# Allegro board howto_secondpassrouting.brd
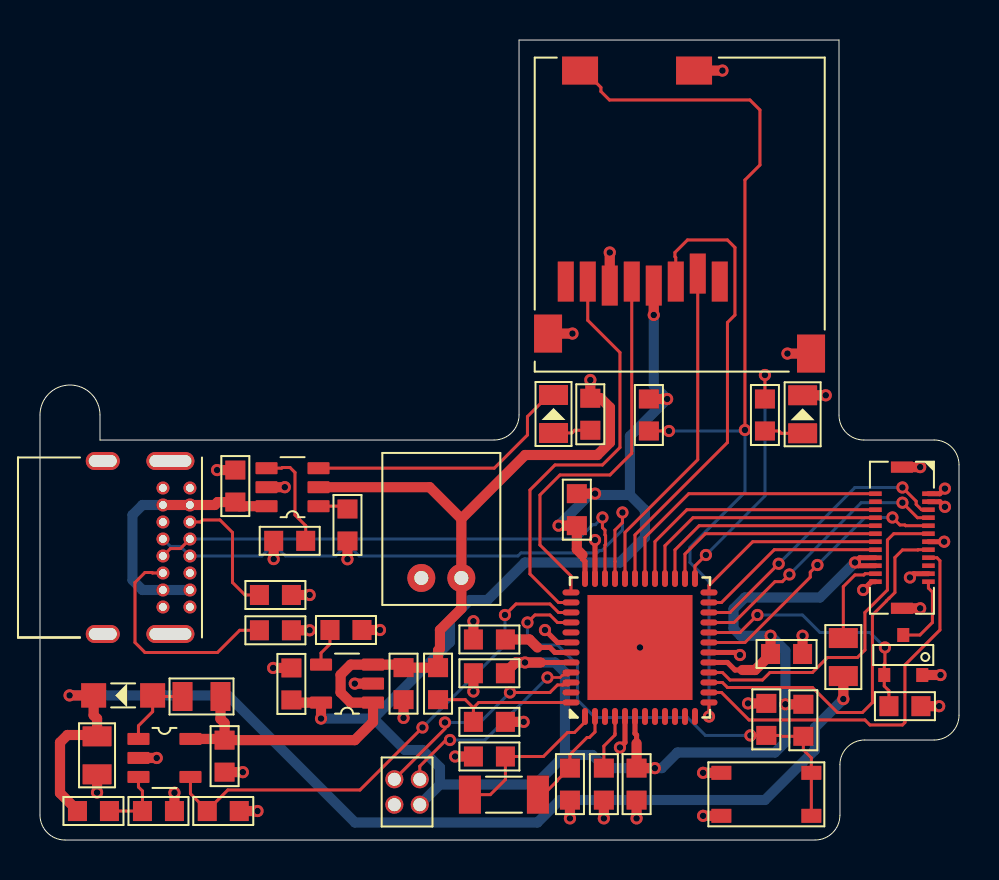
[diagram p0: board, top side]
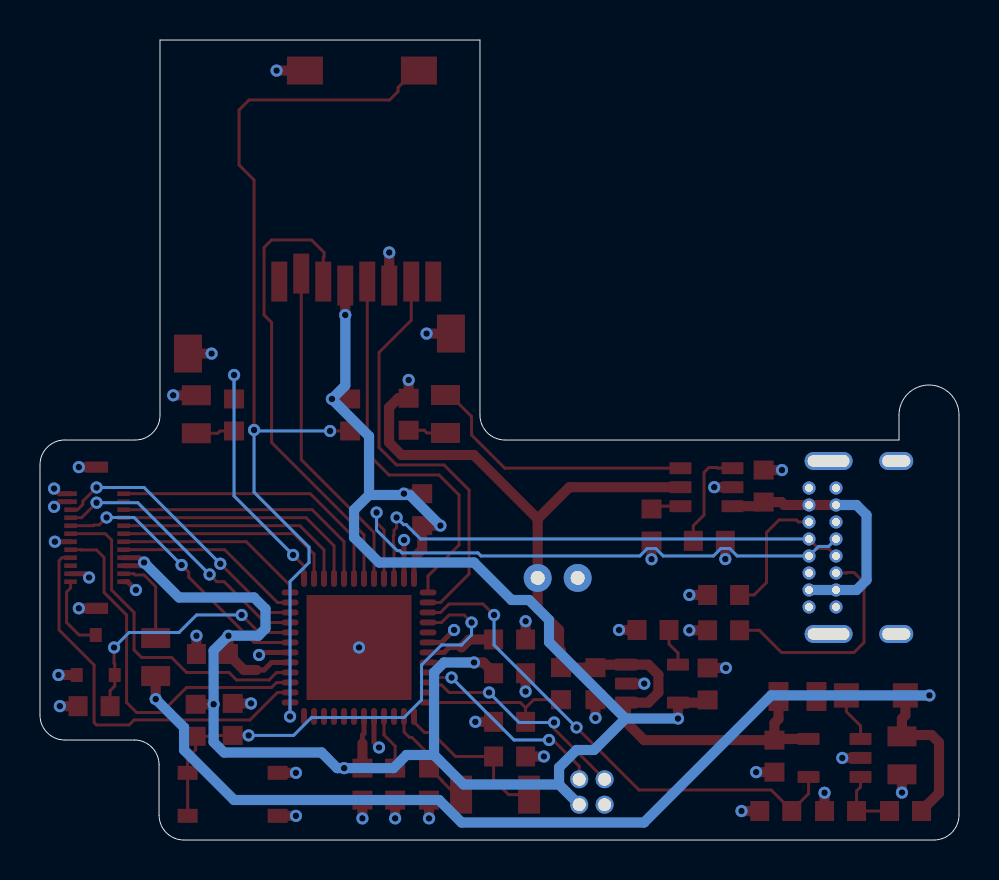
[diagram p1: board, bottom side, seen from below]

Outline 45.95 x 40 mm; copper layers: TOP, L2, L3, BOTTOM. Coordinates in mm from the lower left corner of the outline.
Outline path: 0,21.25 0,1.25 arc(0.37,0.37) 1.25,0 38.76,0 arc(39.64,0.36) 40,1.24 40,3.76 arc(40.36,4.64) 41.24,5 44.71,5 arc(45.59,5.36) 45.95,6.24 45.95,18.76 arc(45.59,19.64) 44.71,20 41.19,20 arc(40.32,20.36) 39.95,21.24 39.95,40 23.95,40 23.95,21.25 arc(23.59,20.37) 22.7,20 3,20 3,21.25 arc(1.5,22.75) 0,21.25

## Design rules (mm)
constraint set DEFAULT: min track width 0.127

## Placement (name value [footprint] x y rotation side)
C15  1uF  [CAP0603]  9.77 17.7 90 top
C16  1uF  [CAP0603]  18.18 7.82 270 top
C19  10uF  [CAP0805]  2.85 4.23 270 top
C20  2.2uF  [CAP0603]  12.57 7.8 90 top
C21  470pF  [CAP0603]  15.3 10.5 0 top
C23  100nF  [CAP0603]  22.47 8.34 180 top
C24  100nF  [CAP0603]  26.84 16.52 90 top
C25  100nF  [CAP0603]  37.33 9.3 0 top
C26  100nF  [CAP0603]  29.83 2.79 270 top
C27  1uF  [CAP0603]  22.47 10.03 180 top
C28  1uF  [CAP0603]  28.2 2.79 270 top
C29  100nF  [CAP0603]  36.32 6.03 90 top
C32  1uF  [CAP0603]  9.23 4.19 270 top
C33  9pF  [CAP0603]  22.47 4.18 180 top
C34  9pF  [CAP0603]  26.5 2.79 270 top
D1  GREEN  [DIO0805]  38.14 21.29 90 top
D2  GREEN  [DIO0805]  25.68 21.3 90 top
D3  SCHOTTKY_DIODE  [SOD-123FL]  4.16 7.23 180 top
J1  -  [USB4085-GF-A]  1.4 14.63 270 top
J2  HEADER VERT 2X2  [2X2-HEADER-50MIL-VERT]  18.36 2.4 270 top
J3  DF37NB-24DS-0.4V  [DF37NB-24DS-0]  43.1 15.11 270 top
J4  2-PIN-CON  [S2B-PH-K]  19.07 13.1 0 top
L1  10uH  [IND0805]  8.08 7.18 180 top
M2  NMOS  [SOT-23-3]  43.17 9.25 0 top
R7  86.6k  [RES0603]  2.67 1.45 0 top
R8  10k  [RES0603]  5.92 1.45 0 top
R9  5.1k  [RES0603]  11.77 12.25 0 top
R10  5.1k  [RES0603]  11.77 10.49 0 top
R11  5.1k  [RES0603]  12.49 14.96 180 top
R12  10k  [RES0603]  38.17 5.99 270 top
R13  10k  [RES0603]  9.16 1.45 0 top
R14  10k  [RES0603]  36.25 21.25 270 top
R15  1.5k  [RES0603]  27.52 21.29 270 top
R16  100k  [RES0603]  19.9 7.82 270 top
R17  100k  [RES0603]  22.47 5.91 0 top
R18  10k  [RES0603]  30.45 21.25 270 top
R19  150R  [RES0805]  40.17 9.15 90 top
R20  10k  [RES0603]  43.25 6.69 0 top
R21  10k  [RES0603]  15.38 15.75 270 top
S1  SPST-NO  [PTS815-SJM-250-SMTR-LFS]  36.32 2.28 0 top
SD2  -  [MEM2061]  30.14 27.92 0 top
U2  BQ21040  [SOT-23-6]  12.63 17.64 180 top
U4  MIC5205-3.3YM5-TR  [SOT-23-5]  15.35 7.82 180 top
U5  AP3012_IC  [SOT-23-5]  6.22 4.1 0 top
U7  ATSAMD21G18A-MF  [48QFN_7X7]  30 9.63 90 top
Y2  32.768 kHz  [2-SMD]  23.2 2.27 0 top

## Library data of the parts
C15 C16 C19-C21 C23-C29 C32-C34 = CAP1: tolerance: 10%
D1 D2 = SML-210MTT86
D3 = SCHOTTKY_DIODE
J1 = USB4085-GF-A
J2 = HEADER VERT 2X2
J3 = DF37NB-24DS-0.4V
J4 = 2-PIN-CON
L1 = IND: tolerance: 20%
M2 = NMOS
R7-R21 = RES1: tolerance: 1%
S1 = PTS815 SJM 250 SMTR LFS
SD2 = MEM2061
U2 = BQ21040
U4 = MIC5205-3.3YM5-TR
U5 = AP3012_IC
U7 = ATSAMD21G18A-MF
Y2 = CC5V-T1A-32.768KHZ-9PF: tolerance: 20%

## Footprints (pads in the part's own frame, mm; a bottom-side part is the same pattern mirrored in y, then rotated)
2-SMD
  rect 1.1x1.9 smd: 1(-1.7,0) 2(1.7,0)
2X2-HEADER-50MIL-VERT
  round 0.9 hole 0.65: 1(-0.635,0.635) 2(-0.635,-0.635) 3(0.635,0.635) 4(0.635,-0.635)
48QFN_7X7
  oval 0.851x0.3 smd: 1(-3.45,2.75) 2(-3.45,2.25) 3(-3.45,1.75) 4(-3.45,1.25) 5(-3.45,0.75) 6(-3.45,0.25) 7(-3.45,-0.25) 8(-3.45,-0.75) 9(-3.45,-1.25) 10(-3.45,-1.75) 11(-3.45,-2.25) 12(-3.45,-2.75) 25(3.45,-2.75) 26(3.45,-2.25) 27(3.45,-1.75) 28(3.45,-1.25) 29(3.45,-0.75) 30(3.45,-0.25) 31(3.45,0.25) 32(3.45,0.75) 33(3.45,1.25) 34(3.45,1.75) 35(3.45,2.25) 36(3.45,2.75)
  oval 0.3x0.851 smd: 13(-2.75,-3.45) 14(-2.25,-3.45) 15(-1.75,-3.45) 16(-1.25,-3.45) 17(-0.75,-3.45) 18(-0.25,-3.45) 19(0.25,-3.45) 20(0.75,-3.45) 21(1.25,-3.45) 22(1.75,-3.45) 23(2.25,-3.45) 24(2.75,-3.45) 37(2.75,3.45) 38(2.25,3.45) 39(1.75,3.45) 40(1.25,3.45) 41(0.75,3.45) 42(0.25,3.45) 43(-0.25,3.45) 44(-0.75,3.45) 45(-1.25,3.45) 46(-1.75,3.45) 47(-2.25,3.45) 48(-2.75,3.45)
  rect 5.25x5.25 smd: 49(0,0)
CAP0603
  rect 0.95x1.001 smd: 1(-0.8,0) 2(0.8,0)
CAP0805
  rrect 1x1.45 smd: 1(-0.95,0) 2(0.95,0)
DF37NB-24DS-0
  rect 0.23x0.63 smd: 1(-2.2,1.325) 2(-2.2,-1.325) 3(-1.8,1.325) 4(-1.8,-1.325) 5(-1.4,1.325) 6(-1.4,-1.325) 7(-1,1.325) 8(-1,-1.325) 9(-0.6,1.325) 10(-0.6,-1.325) 11(-0.2,1.325) 12(-0.2,-1.325) 13(0.2,1.325) 14(0.2,-1.325) 15(0.6,1.325) 16(0.6,-1.325) 17(1,1.325) 18(1,-1.325) 19(1.4,1.325) 20(1.4,-1.325) 21(1.8,1.325) 22(1.8,-1.325) 23(2.2,1.325) 24(2.2,-1.325)
  rect 0.56x1.1 smd: 25(-3.53,0) 26(3.53,0)
DIO0805
  rrect 1x1.45 smd: 1(-0.95,0) 2(0.95,0)
IND0805
  rrect 1x1.45 smd: 1(-0.95,0) 2(0.95,0)
MEM2061
  rect 0.8x2 smd: 1(3.85,0) 2(2.75,0.4) 3(1.65,0) 4(0.55,-0.2) 5(-0.55,0) 6(-1.65,-0.2) 7(-2.75,0) 8(-3.85,0)
  rect 1.4x1.9 smd: P1(-4.735,-2.6) P2(8.415,-3.6)
  rect 1.8x1.4 smd: SW1(-3.135,10.55) SW2(2.565,10.55)
PTS815-SJM-250-SMTR-LFS
  rect 1x0.7 smd: 1(-2.25,1.075) 2(2.25,1.075) 3(-2.25,-1.075) 4(2.25,-1.075)
RES0603
  rect 0.95x1.001 smd: 1(-0.8,0) 2(0.8,0)
RES0805
  rrect 1x1.45 smd: 1(-0.95,0) 2(0.95,0)
S2B-PH-K
  round 1.4 hole 0.7: 1(2,0) 2(0,0)
SOD-123FL
  rect 1.25x1.22 smd: 1(-1.475,0) 2(1.475,0)
SOT-23-3
  rect 0.6x0.7 smd: 1(0.95,-1) 2(0,1) 3(-0.95,-1)
SOT-23-5
  rrect 1.1x0.6 smd: 1(-1.3,0.95) 2(-1.3,0) 3(-1.3,-0.95) 4(1.3,-0.95) 5(1.3,0.95)
SOT-23-6
  rrect 1.1x0.6 smd: 1(-1.3,0.95) 2(-1.3,0) 3(-1.3,-0.95) 4(1.3,-0.95) 5(1.3,0) 6(1.3,0.95)
USB4085-GF-A
  oval 0.9x1.7 hole 0.6x1.4 unplated: (-4.325,1.74) (4.325,1.74)
  round 0.65 hole 0.4: A1(-2.975,6.1) A4(-2.125,6.1) A5(-1.275,6.1) A6(-0.425,6.1) A7(0.425,6.1) A8(1.275,6.1) A9(2.125,6.1) A12(2.975,6.1) B1(2.975,4.75) B4(2.125,4.75) B5(1.275,4.75) B6(0.425,4.75) B7(-0.425,4.75) B8(-1.275,4.75) B9(-2.125,4.75) B12(-2.975,4.75)
  oval 0.9x2.4 hole 0.6x2.1: MNT1(-4.325,5.12) MNT2(4.325,5.12)

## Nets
+3V3: C20.1 C23.1 C24.1 C25.1 C26.1 J2.3 J3.18 J3.20 R12.1 R18.1 SD2.4 U4.5(OUT) U7.6 U7.17 U7.36(VDDIO#36) U7.44
+12V0: C19.1 D3.2 R7.1 R19.1
+VBATT: C16.1 C32.1 J4.1 L1.1 R15.1 R16.1 U2.2 U4.1 U4.3 U5.5(VIN)
+VDDCORE: C27.1 U7.43
GND: C15.2 C16.2 C19.2 C20.2 C21.2 C23.2 C24.2 C25.2 C26.2 C27.2 C28.2 C29.2 C32.2 C33.2 C34.2 D1.2(K) J1.A1 J1.A12 J1.B1 J1.B12 J1.MNT1 J1.MNT2 J2.4 J3.1 J3.3 J3.13 J3.21 J3.24 J3.25 J3.26 J4.2 M2.1(S) R8.2 R9.2 R10.2 R11.2 R13.2 R17.2 R20.2 R21.2 S1.1 S1.3 SD2.6(VSS) SD2.P1 SD2.P2 SD2.SW2 U2.5 U4.2 U5.2 U7.5 U7.18 U7.35 U7.42 U7.49
+V_USB: C15.1 J1.A4 J1.A9 J1.B4 J1.B9(VBUS4) U2.6(VIN)
ADC_VBATT: R16.2 R17.1 U7.48
AREF: C28.1 U7.4
CS*: J3.17 U7.14
D_N: J1.A7 J1.B7 U7.33
D_P: J1.A6 J1.B6 U7.34
DB0: J3.12 U7.26
DB1: J3.11 U7.16
DB2: J3.10 U7.27
DB3: J3.9 U7.19
DB4: J3.8 U7.28
DB5: J3.7 U7.21
DB6: J3.6 U7.29
DB7: J3.5 U7.22
LCD_POWER_EN: R13.1 U5.4 U7.39
LCD_PWM: M2.3 R20.1 U7.20
LCD_RST: J3.2 U7.30
RD*: J3.14 U7.24
RS: J3.16 U7.23
SD_CARD_DETECT: R18.2 SD2.SW1 U7.13
SD_CS: SD2.2 U7.32
SD_MISO: SD2.7 U7.38
SD_MOSI: SD2.3 U7.31
SD_SCK: SD2.5 U7.37
SWCLK: J2.1 U7.45
SWDIO: J2.2 U7.46
WR*: J3.15 U7.15
N42146: J1.A5 R9.1
N42214: R11.1 U2.4
N42218: R21.1 U2.1
N42238: C21.1 U4.4
N42330: J1.B5 R10.1
N42350: D2.1 R15.2
N42414: D2.2(K) U2.3
N42648: D3.1 L1.2 U5.1
N42818: R7.2 R8.1 U5.3
N43960: C33.1 U7.1 Y2.1
N43976: C34.1 U7.2 Y2.2
N44106: C29.1 R12.2 S1.2 S1.4 U7.40
N44702: R14.1 U7.25
N44714: D1.1 R14.2
N46598: J3.22 R19.2
N46734: J3.23 M2.2

Pads without a net: J1 A8 B8; J3 4 19; SD2 1 8; U7 3 7 8 9 10 11 12 41 47

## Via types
v1: diameter 0.61, hole 0.33, TOP to BOTTOM, 81 vias

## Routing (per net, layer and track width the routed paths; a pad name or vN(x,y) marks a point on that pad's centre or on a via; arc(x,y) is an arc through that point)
+3V3: length 107.7
  TOP w0.254: 25.04,8.88 25.7,8.88 U7.44 ; 27.12,14.25 27.12,14.05 27.25,13.93 U7.36 ; J3.18 40.99,14.11 v1(40.75,13.88) 40.91,13.71 J3.20 ; U7.6 29.75,5.33 29.83,5.25 29.83,4.83 ; U7.17 34.3,8.88 34.38,8.88 34.75,8.5 35.12,8.5
  TOP w0.508: 27.12,14.25 26.84,14.53 C24.1 v1(25.93,15.72) ; R18.1 v1(31.36,22.05) ; C23.1 23.27,8.37 23.78,8.88 v1(24.25,8.88) 25.04,8.88 ; v1(14.05,6.07) U4.5 12.71,6.87 C20.1 ; 29.83,4.83 C26.1 v1(30.74,3.59) ; v1(36.53,10.21) C25.1 36.53,9.27 35.76,8.5 35.12,8.5 ; R12.1 v1(37.27,6.79) ; SD2.4 v1(30.69,26.25)
  BOTTOM w0.508: v1(24.25,8.88) 25.75,8.88 26.25,8.38 26.25,4.25 ; 26.25,4.25 27.62,4.25 28.28,3.59 v1(30.74,3.59) 31.09,3.59 31.88,4.38 36.75,4.38 37.27,4.9 v1(37.27,6.79) 37.27,9.47 v1(36.53,10.21) 35.04,10.21 34.68,10.57 34.68,11.55 35.25,12.13 39,12.13 v1(40.75,13.88) ; 26.25,4.25 24.77,2.78 20,2.78 ; J2.3 20,2.78 ; 20,2.78 20,3.63 19.12,4.5 18.25,4.5 16.68,6.07 ; v1(25.93,15.72) 27.46,17.25 29.5,17.25 ; 16.68,6.07 v1(14.05,6.07) ; 16.68,6.07 20.5,9.89 20.5,11 21.5,12 22.38,12 24.25,13.88 29,13.88 30.25,15.13 30.25,16.5 29.5,17.25 ; 29.5,17.25 29.5,20.19 v1(31.36,22.05) 30.69,22.72 v1(30.69,26.25)
+12V0: length 54.8
  TOP w0.508: v1(1.48,7.23) D3.2 2.68,6.24 2.85,6.07 C19.1 2.79,5.25 1.38,5.25 1,4.88 1,2.35 1.87,1.47 R7.1 ; R19.1 v1(40.17,7.04)
  BOTTOM w0.508: v1(1.48,7.23) 9.4,7.23 15.75,0.88 24.88,0.88 26,2 36.25,2 38.75,4.5 38.75,5.63 v1(40.17,7.04)
+VBATT: length 49.2
  TOP w0.508: C32.1 9.17,5.05 U5.5 ; C32.1 9.23,5.85 9.03,6.05 L1.1 ; C32.1 15.74,4.99 16.65,5.9 U4.1 15.54,6.87 15.03,7.38 15.03,8.26 15.54,8.77 U4.3 18.03,8.77 C16.1 R16.1 19.9,9.47 20,9.57 20,10.5 21.07,11.57 J4.1 21.07,16.06 ; 21.07,16.06 19.48,17.64 U2.2 ; 21.07,16.06 24.26,19.25 27.88,19.25 28.5,19.88 28.5,21.63 28.04,22.09 R15.1 v1(27.52,23)
+VDDCORE: length 3.6
  TOP w0.254: 24.88,9.63 25.5,9.63 25.75,9.38 U7.43
  TOP w0.508: C27.1 24.47,10.03 24.88,9.63
GND: length 70.3
  TOP w0.254: v1(41.16,12.5) 41.58,12.91 J3.24 ; 44.42,16.91 44.99,16.91 v1(45.25,16.66) ; v1(35,9.25) 34.87,9.38 U7.18 ; U7.42 25.87,9.88 v1(25.25,10.5) ; v1(45.25,17.57) 44.99,17.31 44.42,17.31 ; 44.42,14.91 v1(45.21,14.91) ; v1(29,4.63) 29.25,4.88 U7.5 ; 44.42,13.31 43.69,13.31 v1(43.5,13.13) ; U7.35 v1(27.75,15) ; U7.49 v1(30,9.63)
  TOP w0.508: D1.2 v1(39.29,22.24) ; S1.3 v1(33.16,1.21) ; U2.5 v1(12.24,17.64) ; C15.2 v1(8.85,18.5) ; SD2.6 v1(28.49,29.38) ; SD2.P2 v1(37.38,24.32) ; R13.2 v1(10.88,1.45) ; SD2.SW2 v1(34.12,38.47) ; R17.2 v1(24.18,5.91) ; C27.2 v1(21.67,10.94) ; J3.26 v1(44.01,11.58) ; J3.25 v1(44.01,18.64) ; C21.2 v1(17,10.5) ; C23.2 v1(21.67,7.43) ; C16.2 v1(18.18,6.1) ; C29.2 v1(35.41,6.83) ; U5.2 v1(5.84,4.1) ; R20.2 v1(44.96,6.69) ; R10.2 v1(13.48,10.49) ; C20.2 v1(11.66,8.6) ; R8.2 v1(6.72,2.36) ; C25.2 v1(38.13,10.21) ; R9.2 v1(13.48,12.25) ; S1.1 v1(33.16,3.36) ; U4.2 v1(15.74,7.82) ; C32.2 v1(10.14,3.39) ; C34.2 v1(26.5,1.08) ; C33.2 v1(20.76,4.18) ; 44.12,8.25 v1(45.03,8.25) ; C24.2 v1(27.76,17.32) ; C26.2 v1(29.83,1.08) ; C28.2 v1(28.2,1.08) ; C19.2 v1(2.85,2.37) ; R11.2 v1(11.69,14.05) ; R21.2 v1(15.38,14.04) ; SD2.P1 v1(26.62,25.32)
  L2 w0.508: 17.09,1.77 J2.4 17.72,1.14 ; J1.MNT1 7.9,18.95 ; J1.MNT1 6.52,18.32 ; J1.MNT1 5.14,18.95 ; 7.5,11.15 J1.A12 ; J1.A12 8,11.65 ; J1.A12 7,11.65 ; J1.A1 7.5,18.1 ; J1.A1 7,17.6 ; J1.A1 8,17.6 ; 6.52,9.67 J1.MNT2 ; J1.MNT2 7.9,10.3 ; J1.MNT2 5.14,10.3 ; J1.MNT2 6.52,10.93 ; 6.15,11.15 J1.B1 ; J1.B1 6.65,11.65 ; J1.B1 5.65,11.65 ; 2.11,10.3 3.14,10.3 ; 3.14,10.3 3.14,10.93 ; 3.14,10.3 4.17,10.3 ; 3.14,10.3 3.14,9.67 ; 3.14,18.95 4.17,18.95 ; 3.14,18.95 2.11,18.95 ; 3.14,18.95 3.14,18.32 ; J4.2 19.95,13.1 ; J4.2 18.19,13.1 ; J4.2 19.07,13.98 ; J4.2 19.07,12.22 ; J1.B12 6.65,17.6 ; J1.B12 5.65,17.6 ; J1.B12 6.15,18.1
+V_USB: length 13.4
  TOP w0.508: J1.B9 J1.A4 8.74,16.75 8.89,16.9 C15.1 9.97,16.69 U2.6
  BOTTOM w0.508: J1.A9 J1.B4 5.13,12.5 4.62,13 4.62,16.25 5.12,16.75 J1.B9
ADC_VBATT: length 7.6
  TOP w0.15: 21.67,6.61 R17.1 ; 21.67,6.61 21.94,6.88 U7.48 ; 21.67,6.61 21.26,7.02 R16.2
AREF: length 2.8
  TOP w0.15: U7.4 28.75,5.33 28.75,5.32 28.75,5.25 28.2,4.7 C28.1
CS*: length 20
  TOP w0.15: 44.42,14.11 44.85,14.11 45,13.96 45,10.5 43.25,8.75 43.25,5.88 43.12,5.75 41.5,5.75 41.25,6 35.46,6 34.08,7.38 U7.14
D_N: length 28.8
  TOP w0.15: U7.33 28.75,13.93 28.75,13.93 28.75,15.49 29.12,15.87 v1(29.12,16.38)
  BOTTOM w0.15: J1.B7 6.52,14.68 7.02,14.68 J1.A7 11.09,14.2 11.47,14.58 11.9,14.58 12.28,14.2 14.79,14.2 15.16,14.57 15.59,14.57 15.96,14.2 23.9,14.2 24.05,14.35 27.85,14.35 27.97,14.47 28.09,14.47 29.12,15.5 v1(29.12,16.38)
D_P: length 25.9
  TOP w0.15: J1.A6 7.02,14.57 6.52,14.57 J1.B6 ; U7.34 28.25,14.75 28.28,14.78 28.28,15.22 28.25,15.25 28.25,15.49 28.12,15.62 v1(28.12,16.13)
  BOTTOM w0.15: J1.A6 26.92,15.05 27.64,15.77 27.77,15.77 v1(28.12,16.13)
DB0: length 11.2
  TOP w0.15: J3.12 33.27,15.31 32.25,14.3 U7.26
DB1: length 16.7
  TOP w0.15: U7.16 34.12,8.38 34.5,8 36.12,8 36.5,8.38 38.62,8.38 39.38,9.13 40.88,9.13 41.25,9.5 41.25,11.38 42.38,12.5 42.38,15 42.69,15.31 44.42,15.31
DB2: length 12
  TOP w0.15: J3.10 32.96,15.71 31.75,14.51 U7.27
DB3: length 13.9
  TOP w0.15: v1(38.88,13.75) 38.52,13.39 38.52,13.14 35.25,9.88 U7.19 ; v1(42.62,16.13) 43,15.75 43.25,15.75 43.29,15.71 44.42,15.71
  BOTTOM w0.15: v1(38.88,13.75) 41.25,16.13 v1(42.62,16.13)
DB4: length 12.7
  TOP w0.15: J3.8 32.65,16.11 31.25,14.71 U7.28
DB5: length 13.8
  TOP w0.15: 44.42,16.11 43.88,16.11 v1(43.12,16.87) ; v1(37.47,13.28) 37.12,12.92 36.75,12.92 34.71,10.88 U7.21
  BOTTOM w0.15: v1(43.12,16.87) 41.06,16.87 v1(37.47,13.28)
DB6: length 13.5
  TOP w0.15: J3.6 32.35,16.51 30.75,14.92 U7.29
DB7: length 14.1
  TOP w0.15: v1(43.12,17.63) 43.81,16.94 43.81,16.78 44.08,16.51 44.42,16.51 ; U7.22 34.5,11.38 v1(36.94,13.81)
  BOTTOM w0.15: v1(43.12,17.63) 40.75,17.63 v1(36.94,13.81)
LCD_POWER_EN: length 25.6
  TOP w0.15: 8.36,1.47 7.52,2.31 U5.4 ; 8.36,1.47 R13.1 ; 8.36,1.47 9.39,2.5 16,2.5 v1(19.12,5.63) ; U7.39 25.92,11.38 25.5,11.8 23.8,11.8 v1(23.25,11.25)
  BOTTOM w0.15: v1(19.12,5.63) 23.25,9.75 v1(23.25,11.25)
LCD_PWM: length 12.9
  TOP w0.15: U7.20 35,10.38 v1(35.88,11.25) ; v1(42.25,9.63) 42.25,8.83 42.22,8.8 M2.3 42.22,7.7 42.45,7.46 R20.1
  BOTTOM w0.15: v1(35.88,11.25) 38.12,11.25 39,10.38 41.5,10.38 v1(42.25,9.63)
LCD_RST: length 14.5
  TOP w0.15: J3.2 32.44,17.31 30.25,15.13 U7.30
RD*: length 9.6
  TOP w0.15: J3.14 35.64,14.91 33.45,12.73 U7.24
RS: length 9.4
  TOP w0.15: U7.23 34.08,11.88 36.72,14.51 J3.16
SD_CARD_DETECT: length 47.6
  TOP w0.15: U7.13 v1(33.45,6.17) ; v1(35.25,20.5) 35.25,33 36,33.75 36,36.5 35.5,37 28.48,37 28.05,37.43 28.05,37.63 27.21,38.47 SD2.SW1 ; R18.2 v1(31.45,20.45)
  BOTTOM w0.15: v1(33.45,6.17) 33.45,12.92 32.5,13.88 32.5,14.64 35.25,17.39 v1(35.25,20.5) 35.2,20.45 v1(31.45,20.45)
SD_CS: length 16.8
  TOP w0.15: U7.32 29.25,15.38 32.89,19.02 SD2.2
SD_MISO: length 21.2
  TOP w0.15: U7.38 25.92,11.88 24.5,13.3 24.5,17.5 25.75,18.75 28.12,18.75 29,19.63 29,24.38 27.39,25.99 SD2.7
SD_MOSI: length 23.5
  TOP w0.15: SD2.3 31.79,29.12 31.75,29.16 31.75,29.38 32.38,30 34.38,30 34.75,29.63 34.75,26.25 34.38,25.88 34.38,19.88 29.75,15.25 U7.31
SD_SCK: length 19.6
  TOP w0.15: SD2.5 29.59,19.34 28.5,18.25 26,18.25 25,17.25 25,14.75 26.55,13.2 U7.37
SWCLK: length 10.2
  TOP w0.127: U7.45 26.42,8.24 26.13,8.24 26.01,8.13 v1(25.38,8.13)
  TOP w0.15: v1(20.5,5) 20.3,5 18.99,3.69 J2.1
  BOTTOM w0.15: v1(20.5,5) 22.25,5 v1(25.38,8.13)
SWDIO: length 11
  TOP w0.15: v1(20.25,5.88) 20.25,5.57 J2.2 ; v1(23.5,7.38) 25.5,7.38 25.88,7.75 26.12,7.75 26.12,7.75 26.43,7.75 U7.46
  BOTTOM w0.15: v1(23.5,7.38) 22,5.88 v1(20.25,5.88)
WR*: length 18.6
  TOP w0.15: U7.15 34.12,7.88 34.38,7.63 38.63,7.63 39.88,6.38 41.12,6.38 41.62,6.88 41.62,11.25 42.32,11.95 42.32,11.96 42.46,12.09 42.46,12.09 42.75,12.38 42.75,14.13 43.12,14.5 43.89,14.5 43.91,14.51 44.42,14.51
N42146: length 6.5
  TOP w0.15: J1.A5 8.03,15.9 8.13,16 9,16 9.62,15.38 9.62,12.88 10.25,12.25 R9.1
N42214: length 5.2
  TOP w0.15: R11.1 13.29,15.71 12.75,16.25 12.75,18.38 12.5,18.63 12.11,18.63 12.08,18.59 U2.4
N42218: length 1.5
  TOP w0.15: R21.1 15.23,16.69 U2.1
N42238: length 1.9
  TOP w0.15: U4.4 14.05,9.35 14.5,9.8 C21.1
N42330: length 11.5
  TOP w0.15: R10.1 9.99,10.49 8.88,9.38 5.25,9.38 4.75,9.88 4.75,12.88 5.25,13.38 5.6,13.38 5.62,13.35 J1.B5
N42350: length 1.9
  TOP w0.15: R15.2 26.74,20.49 26.61,20.35 D2.1
N42414: length 13.8
  TOP w0.15: D2.2 25.45,22.25 24.38,21.17 24.38,20.25 22.72,18.59 U2.3
N42648: length 4
  TOP w0.15: U5.1 4.92,5.71 5.63,6.42 D3.1 5.69,7.18 L1.2
N42818: length 3.4
  TOP w0.15: U5.3 4.92,2.65 5.12,2.45 R8.1 R7.2
N43960: length 8.2
  TOP w0.15: U7.1 27.25,5.9 26.73,5.38 26.38,5.38 25.18,4.18 C33.1 23.27,3.02 22.52,2.27 Y2.1
N43976: length 5.3
  TOP w0.15: Y2.2 25.17,2.27 25.86,2.95 25.86,2.98 26.47,3.59 C34.1 26.5,4.27 27.35,5.13 27.48,5.13 27.75,5.4 U7.2
N44106: length 24.2
  TOP w0.15: S1.4 S1.2 38.57,4.11 38.17,4.51 R12.2 37.06,5.19 37.02,5.23 C29.1 v1(35.52,5.23) ; v1(24.38,10.88) 24.75,11.25 25.5,11.25 25.88,10.88 U7.40
  BOTTOM w0.15: v1(24.38,10.88) 24.38,10.25 24.88,9.75 25.88,9.75 26.88,8.75 26.88,7 27.75,6.13 32.38,6.13 33.27,5.23 v1(35.52,5.23)
N44702: length 12.8
  TOP w0.15: v1(33.3,14.25) 32.75,13.7 U7.25 ; v1(36.25,23.25) R14.1
  BOTTOM w0.15: v1(33.3,14.25) 36.25,17.2 v1(36.25,23.25)
N44714: length 1.9
  TOP w0.15: D1.1 37.07,20.34 36.95,20.45 R14.2
N46598: length 4.4
  TOP w0.15: R19.2 40.17,12.67 40.75,13.25 41.19,13.25 41.26,13.31 J3.22
N46734: length 3.8
  TOP w0.15: M2.2 44,10.25 44.62,10.88 44.62,12.4 44.42,12.6 44.42,12.91

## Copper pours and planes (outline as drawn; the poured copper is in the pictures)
GND on L2: 24.21,39.75 39.7,39.75 39.7,21.24 40.14,20.18 41.19,19.75 44.71,19.75 45.7,18.76 45.7,6.24 44.71,5.25 41.24,5.25 40.18,4.82 39.75,3.76 39.75,1.24 38.76,0.25 1.25,0.25 0.25,1.25 0.25,21.25 2.75,21.25 2.75,19.75 22.7,19.75 23.77,20.19 24.21,21.25
